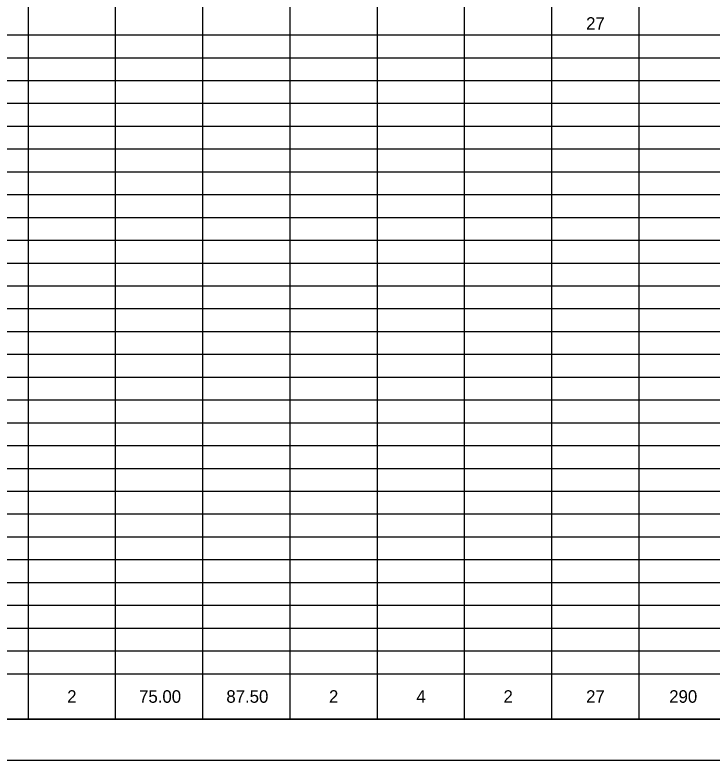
# Model space of a CAD drawing. Extents: x 0 to 34, y 0 to 22.
# Drawn here: x 16.87 to 25.41, y 0 to 9.13 of the extents above; entities that cross this region are included whole.
import ezdxf

# ---------------------------------------------------------------- set-up
doc = ezdxf.new("R2010")
doc.units = 0
for name, color, linetype in [('SH_Border', 7, 'Continuous'), ('SH_Cut_Line', 7, 'Continuous'), ('SH_Data', 7, 'Continuous'), ('SH_Text', 7, 'Continuous')]:
    doc.layers.add(name, color=color, linetype=linetype)

msp = doc.modelspace()

# ---------------------------------------------------------------- linework, layer by layer
at = {"layer": 'SH_Border'}
msp.add_lwpolyline([(1.5, 21.5), (33.5, 21.5), (33.5, 0.5), (1.5, 0.5)], close=True, dxfattribs=at)
at = {"layer": 'SH_Cut_Line'}
msp.add_lwpolyline([(0, 0), (34, 0), (34, 22), (0, 22)], close=True, dxfattribs=at)
at = {"layer": 'SH_Data'}
for p, q in [((17.0294, 21.4753), (17.0294, 0.5)), ((18.0988, 21.4753), (18.0988, 0.5)), ((19.1681, 21.4753), (19.1681, 0.5)), ((20.2374, 21.4753), (20.2374, 0.5)), ((21.3067, 21.4753), (21.3067, 0.5)), ((22.3761, 21.4753), (22.3761, 0.5)), ((23.4454, 21.4753), (23.4454, 0.5)), ((24.5147, 21.4753), (24.5147, 0.5)), ((1.4831, 8.8901), (32, 8.8901)), ((1.4831, 8.6104), (32, 8.6104)), ((1.4831, 8.3308), (32, 8.3308)), ((1.4831, 8.0511), (32, 8.0511)), ((1.4831, 7.7714), (32, 7.7714)), ((1.4831, 7.4918), (32, 7.4918)), ((1.4831, 7.2121), (32, 7.2121)), ((1.4831, 6.9324), (32, 6.9324)), ((1.4831, 6.6527), (32, 6.6527)), ((1.4831, 6.3731), (32, 6.3731)), ((1.4831, 6.0934), (32, 6.0934)), ((1.4831, 5.8137), (32, 5.8137)), ((1.4831, 5.5341), (32, 5.5341)), ((1.4831, 5.2544), (32, 5.2544)), ((1.4831, 4.9747), (32, 4.9747)), ((1.4831, 4.6951), (32, 4.6951)), ((1.4831, 4.4154), (32, 4.4154)), ((1.4831, 4.1357), (32, 4.1357)), ((1.4831, 3.856), (32, 3.856)), ((1.4831, 3.5764), (32, 3.5764)), ((1.4831, 3.2967), (32, 3.2967)), ((1.4831, 3.017), (32, 3.017)), ((1.4831, 2.7374), (32, 2.7374)), ((1.4831, 2.4577), (32, 2.4577)), ((1.4831, 2.178), (32, 2.178)), ((1.4831, 1.8984), (32, 1.8984)), ((1.4831, 1.6187), (32, 1.6187)), ((1.4831, 1.339), (32, 1.339)), ((1.4831, 1.0593), (32, 1.0593)), ((1.4831, 0.5), (32, 0.5))]:
    msp.add_line(p, q, dxfattribs=at)

# ---------------------------------------------------------------- texts
at = {"layer": 'SH_Text'}
for s, height, p in [('27', 0.15382, (23.8687, 8.953)), ('2', 0.1538, (17.5097, 0.7028)), ('75.00', 0.15382, (18.3906, 0.7028)), ('87.50', 0.15382, (19.46, 0.7028)), ('2', 0.1538, (20.7177, 0.7028)), ('4', 0.1538, (21.7888, 0.7028)), ('2', 0.1538, (22.8564, 0.7028)), ('27', 0.15382, (23.8687, 0.7028)), ('290', 0.15382, (24.8872, 0.7028))]:
    msp.add_text(s, height=height, dxfattribs=at).set_placement(p)

doc.saveas('drawing.dxf')
